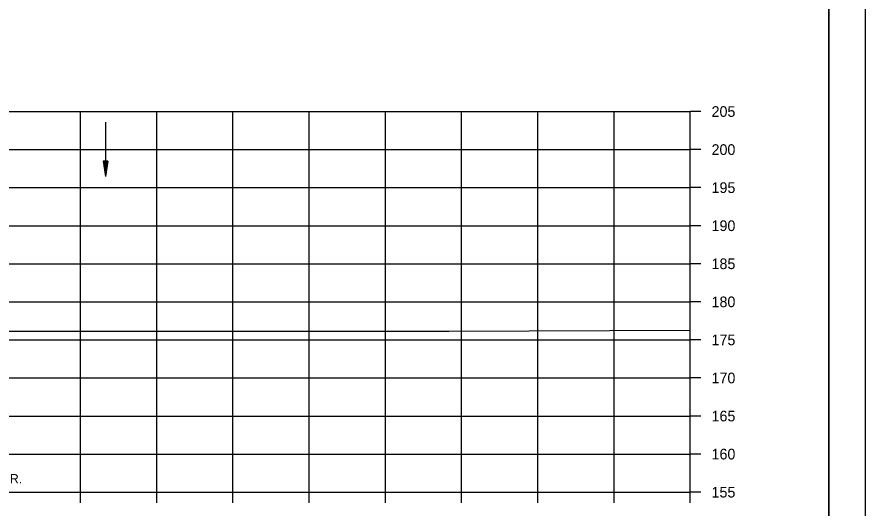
# Model space of a CAD drawing. Extents: x 1372132 to 1372465, y 380083 to 381790.
# Drawn here: x 1372353.7 to 1372464.9, y 381233.1 to 381297.6 of the extents above; entities that cross this region are included whole.
import ezdxf

# ---------------------------------------------------------------- set-up
doc = ezdxf.new("R2010")
doc.units = 0
for name, color, linetype in [('R_Axis', 7, 'Continuous'), ('R_Axis Annot', 7, 'Continuous'), ('R_Border', 7, 'Continuous'), ('R_Dimension', 7, 'Continuous'), ('R_Draft', 7, 'Continuous'), ('R_Exist Surface', 7, 'Continuous'), ('R_Grid', 7, 'Continuous'), ('R_No Plot', 7, 'Continuous')]:
    doc.layers.add(name, color=color, linetype=linetype)

msp = doc.modelspace()

# ---------------------------------------------------------------- linework, layer by layer
at = {"layer": 'R_Axis'}
for p, q in [((1372442.01, 381235.16), (1372442.01, 381285.16)), ((1372443.41, 381285.16), (1372442.01, 381285.16)), ((1372443.41, 381280.16), (1372442.01, 381280.16)), ((1372443.41, 381275.16), (1372442.01, 381275.16)), ((1372443.41, 381270.16), (1372442.01, 381270.16)), ((1372443.41, 381265.16), (1372442.01, 381265.16)), ((1372443.41, 381260.16), (1372442.01, 381260.16)), ((1372443.41, 381255.16), (1372442.01, 381255.16)), ((1372443.41, 381250.16), (1372442.01, 381250.16)), ((1372443.41, 381245.16), (1372442.01, 381245.16)), ((1372443.41, 381240.16), (1372442.01, 381240.16)), ((1372162.01, 381235.16), (1372442.01, 381235.16)), ((1372362.01, 381233.76), (1372362.01, 381235.16)), ((1372372.01, 381233.76), (1372372.01, 381235.16)), ((1372382.01, 381233.76), (1372382.01, 381235.16)), ((1372392.01, 381233.76), (1372392.01, 381235.16)), ((1372402.01, 381233.76), (1372402.01, 381235.16)), ((1372412.01, 381233.76), (1372412.01, 381235.16)), ((1372422.01, 381233.76), (1372422.01, 381235.16)), ((1372432.01, 381233.76), (1372432.01, 381235.16)), ((1372442.01, 381233.76), (1372442.01, 381235.16)), ((1372443.41, 381235.16), (1372442.01, 381235.16))]:
    msp.add_line(p, q, dxfattribs=at)
at = {"layer": 'R_Border'}
msp.add_line((1372460.19, 381154.16), (1372460.19, 381359.62), dxfattribs=at)
at = {"layer": 'R_Dimension'}
for p, q in [((1372365, 381278.62), (1372365.3, 381276.62)), ((1372365.6, 381278.62), (1372365, 381278.62)), ((1372365, 381278.62), (1372365.3, 381276.62)), ((1372365.6, 381278.62), (1372365, 381278.62)), ((1372365.05, 381278.62), (1372365.3, 381276.96)), ((1372365.05, 381278.62), (1372365.3, 381276.96)), ((1372365.1, 381278.62), (1372365.3, 381277.3)), ((1372365.1, 381278.62), (1372365.3, 381277.3)), ((1372365.15, 381278.62), (1372365.3, 381277.63)), ((1372365.15, 381278.62), (1372365.3, 381277.63)), ((1372365.2, 381278.62), (1372365.3, 381277.97)), ((1372365.2, 381278.62), (1372365.3, 381277.97)), ((1372365.26, 381278.62), (1372365.3, 381278.31)), ((1372365.26, 381278.62), (1372365.3, 381278.31)), ((1372365.6, 381278.62), (1372365.3, 381276.62)), ((1372365.4, 381278.62), (1372365.3, 381277.97)), ((1372365.5, 381278.62), (1372365.3, 381277.3)), ((1372365.55, 381278.62), (1372365.3, 381276.96)), ((1372365.45, 381278.62), (1372365.3, 381277.63)), ((1372365.35, 381278.62), (1372365.3, 381278.31)), ((1372365.6, 381278.62), (1372365.3, 381276.62)), ((1372365.4, 381278.62), (1372365.3, 381277.97)), ((1372365.5, 381278.62), (1372365.3, 381277.3)), ((1372365.55, 381278.62), (1372365.3, 381276.96)), ((1372365.45, 381278.62), (1372365.3, 381277.63)), ((1372365.35, 381278.62), (1372365.3, 381278.31))]:
    msp.add_line(p, q, dxfattribs=at)
at = {"layer": 'R_Draft'}
msp.add_line((1372365.3, 381283.76), (1372365.3, 381276.62), dxfattribs=at)
at = {"layer": 'R_Exist Surface'}
msp.add_lwpolyline([(1372348.18, 381256.33), (1372373.04, 381256.32), (1372405.24, 381256.29), (1372410.35, 381256.31), (1372442.01, 381256.43)], dxfattribs=at)
at = {"layer": 'R_Grid'}
for p, q in [((1372162.01, 381285.16), (1372442.01, 381285.16)), ((1372362.01, 381235.16), (1372362.01, 381285.16)), ((1372372.01, 381235.16), (1372372.01, 381285.16)), ((1372382.01, 381235.16), (1372382.01, 381285.16)), ((1372392.01, 381235.16), (1372392.01, 381285.16)), ((1372402.01, 381235.16), (1372402.01, 381285.16)), ((1372412.01, 381235.16), (1372412.01, 381285.16)), ((1372422.01, 381235.16), (1372422.01, 381285.16)), ((1372432.01, 381235.16), (1372432.01, 381285.16)), ((1372442.01, 381235.16), (1372442.01, 381285.16)), ((1372162.01, 381280.16), (1372442.01, 381280.16)), ((1372162.01, 381275.16), (1372442.01, 381275.16)), ((1372162.01, 381270.16), (1372442.01, 381270.16)), ((1372162.01, 381265.16), (1372442.01, 381265.16)), ((1372162.01, 381260.16), (1372442.01, 381260.16)), ((1372162.01, 381255.16), (1372442.01, 381255.16)), ((1372162.01, 381250.16), (1372442.01, 381250.16)), ((1372162.01, 381245.16), (1372442.01, 381245.16)), ((1372162.01, 381240.16), (1372442.01, 381240.16)), ((1372162.01, 381235.16), (1372442.01, 381235.16))]:
    msp.add_line(p, q, dxfattribs=at)
at = {"layer": 'R_No Plot'}
for points in [[(1372131.61, 381363.52), (1372464.95, 381363.52), (1372464.95, 381150.18), (1372131.61, 381150.18)], [(1372377.93, 381359.62), (1372377.93, 381349.74), (1372413.67, 381349.74), (1372413.67, 381346.82), (1372436.87, 381346.82), (1372436.87, 381322.49), (1372460.19, 381322.49), (1372460.19, 381154.16), (1372144.01, 381154.16), (1372144.01, 381359.62)]]:
    msp.add_lwpolyline(points, close=True, dxfattribs=at)

# ---------------------------------------------------------------- texts
at = {"layer": 'R_Axis Annot'}
for s, p in [('205', (1372444.81, 381284.46)), ('200', (1372444.81, 381279.46)), ('195', (1372444.81, 381274.46)), ('190', (1372444.81, 381269.46)), ('185', (1372444.81, 381264.46)), ('180', (1372444.81, 381259.46)), ('175', (1372444.81, 381254.46)), ('170', (1372444.81, 381249.46)), ('165', (1372444.81, 381244.46)), ('160', (1372444.81, 381239.46)), ('155', (1372444.81, 381234.46))]:
    msp.add_text(s, height=1.4, dxfattribs=at).set_placement(p)
at = {"layer": 'R_Draft'}
msp.add_text('END 2.18% RT. DT. GR.', height=1.2, dxfattribs=at).set_placement((1372336.61, 381236.33))

doc.saveas('drawing.dxf')
